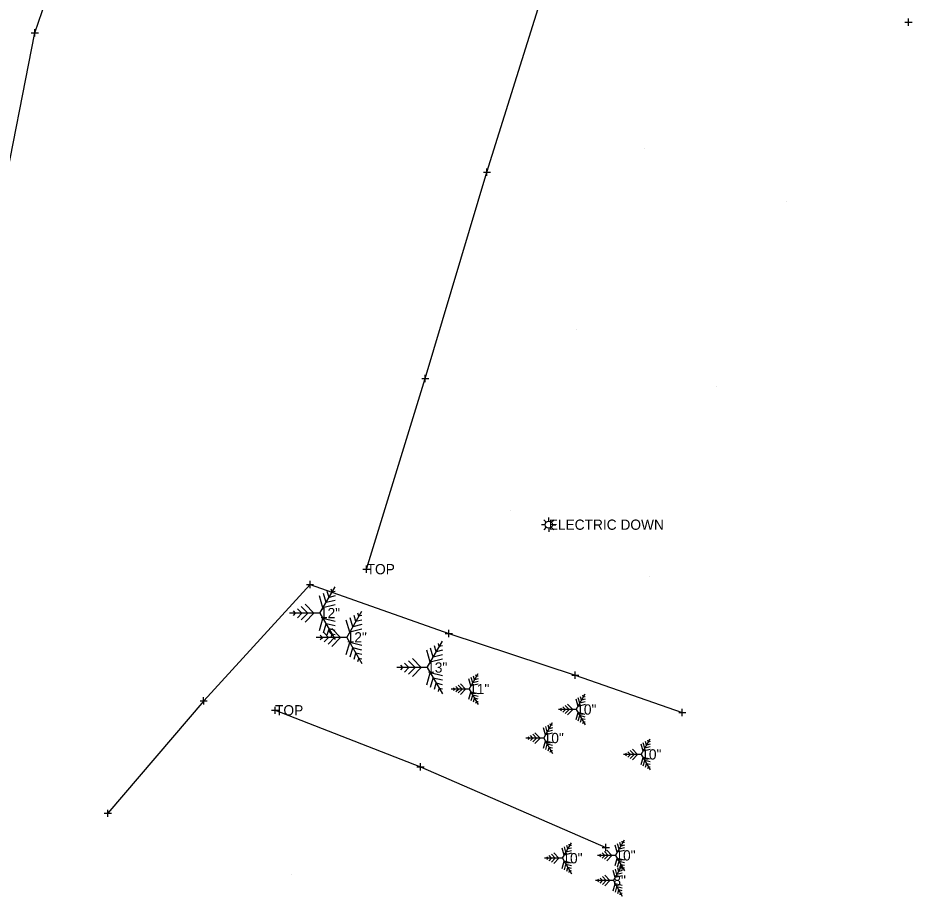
# Model space of a CAD drawing. Extents: x 1733239 to 1734352, y 466612 to 468622.
# Drawn here: x 1733888.4 to 1734045.2, y 467838.1 to 467992.2 of the extents above; entities that cross this region are included whole.
import ezdxf

# ---------------------------------------------------------------- set-up
doc = ezdxf.new("R2010")
doc.units = 0
for name, color, linetype in [('S_Terrain_Boundary', 7, 'Continuous'), ('S_Terrain_High_Points', 7, 'Continuous'), ('S_Terrain_Holes', 7, 'Continuous'), ('S_Terrain_Islands', 7, 'Continuous'), ('S_Terrain_Low_Points', 7, 'Continuous'), ('S_Terrain_Major_Contours', 7, 'Continuous'), ('S_Terrain_Major_Contours_Label', 7, 'Continuous'), ('S_Terrain_Minor_Contours', 7, 'Continuous'), ('S_Traffic_Sign_SinglePost', 7, 'Continuous')]:
    doc.layers.add(name, color=color, linetype=linetype)

msp = doc.modelspace()

# ---------------------------------------------------------------- linework, layer by layer
at = {"layer": 'S_Terrain_Boundary'}
for points in [[(1733939.58, 467892.77), (1733920.94, 467872.37), (1733904.15, 467852.65)], [(1733939.58, 467892.77), (1733963.92, 467884.2), (1733986.1, 467876.86), (1734004.85, 467870.32)]]:
    msp.add_lwpolyline(points, dxfattribs=at)
at = {"layer": 'S_Terrain_High_Points'}
for p, q in [((1733941.32, 467887.77), (1733943.98, 467892.38)), ((1733941.85, 467888.69), (1733941.24, 467890.79)), ((1733942.39, 467889.61), (1733941.93, 467891.19)), ((1733942.91, 467890.53), (1733942.61, 467891.59)), ((1733943.98, 467890.79), (1733942.91, 467890.53)), ((1733943.45, 467891.45), (1733943.3, 467891.98)), ((1733943.98, 467891.59), (1733943.45, 467891.45)), ((1733939.19, 467887.77), (1733938.05, 467888.95)), ((1733940.25, 467887.77), (1733938.73, 467889.35)), ((1733943.98, 467889.21), (1733941.85, 467888.69)), ((1733943.98, 467890.01), (1733942.39, 467889.61)), ((1733941.32, 467887.77), (1733936, 467887.77)), ((1733937.06, 467887.77), (1733936.68, 467888.16)), ((1733936.68, 467887.37), (1733937.06, 467887.77)), ((1733938.12, 467887.77), (1733937.37, 467888.55)), ((1733937.37, 467886.97), (1733938.12, 467887.77)), ((1733938.05, 467886.58), (1733939.19, 467887.77)), ((1733938.73, 467886.18), (1733940.25, 467887.77)), ((1733941.32, 467887.77), (1733943.98, 467883.15)), ((1733946.01, 467883.52), (1733948.67, 467888.13)), ((1733948.13, 467887.21), (1733947.98, 467887.74)), ((1733941.24, 467884.74), (1733941.85, 467886.84)), ((1733943.98, 467886.32), (1733941.85, 467886.84)), ((1733941.93, 467884.34), (1733942.39, 467885.92)), ((1733943.98, 467885.52), (1733942.39, 467885.92)), ((1733946.54, 467884.44), (1733945.93, 467886.55)), ((1733947.07, 467885.36), (1733946.61, 467886.94)), ((1733947.6, 467886.28), (1733947.3, 467887.34)), ((1733948.67, 467886.55), (1733947.6, 467886.28)), ((1733948.67, 467887.34), (1733948.13, 467887.21)), ((1733942.81, 467883.52), (1733942.05, 467884.31)), ((1733942.61, 467883.94), (1733942.91, 467885)), ((1733943.88, 467883.52), (1733942.74, 467884.7)), ((1733943.98, 467884.74), (1733942.91, 467885)), ((1733944.94, 467883.52), (1733943.42, 467885.1)), ((1733948.67, 467884.97), (1733946.54, 467884.44)), ((1733948.67, 467885.76), (1733947.07, 467885.36)), ((1733946.01, 467883.52), (1733940.68, 467883.52)), ((1733941.74, 467883.52), (1733941.37, 467883.91)), ((1733941.37, 467883.12), (1733941.74, 467883.52)), ((1733942.05, 467882.73), (1733942.81, 467883.52)), ((1733942.74, 467882.33), (1733943.88, 467883.52)), ((1733943.3, 467883.55), (1733943.45, 467884.08)), ((1733943.42, 467881.94), (1733944.94, 467883.52)), ((1733943.98, 467883.94), (1733943.45, 467884.08)), ((1733946.01, 467883.52), (1733948.67, 467878.91)), ((1733960.12, 467878.23), (1733962.79, 467882.84)), ((1733945.93, 467880.49), (1733946.54, 467882.6)), ((1733948.67, 467882.07), (1733946.54, 467882.6)), ((1733946.61, 467880.09), (1733947.07, 467881.67)), ((1733948.67, 467881.28), (1733947.07, 467881.67)), ((1733960.66, 467879.15), (1733960.05, 467881.25)), ((1733961.19, 467880.07), (1733960.73, 467881.65)), ((1733961.72, 467880.99), (1733961.42, 467882.05)), ((1733962.79, 467881.25), (1733961.72, 467880.99)), ((1733962.25, 467881.91), (1733962.1, 467882.44)), ((1733962.79, 467882.05), (1733962.25, 467881.91)), ((1733947.3, 467879.7), (1733947.6, 467880.75)), ((1733948.67, 467880.49), (1733947.6, 467880.75)), ((1733947.98, 467879.3), (1733948.13, 467879.83)), ((1733948.67, 467879.7), (1733948.13, 467879.83)), ((1733959.06, 467878.23), (1733957.54, 467879.81)), ((1733962.79, 467879.67), (1733960.66, 467879.15)), ((1733962.79, 467880.47), (1733961.19, 467880.07)), ((1733960.12, 467878.23), (1733954.8, 467878.23)), ((1733955.86, 467878.23), (1733955.49, 467878.62)), ((1733955.49, 467877.83), (1733955.86, 467878.23)), ((1733956.93, 467878.23), (1733956.17, 467879.01)), ((1733956.17, 467877.43), (1733956.93, 467878.23)), ((1733958, 467878.23), (1733956.85, 467879.41)), ((1733956.85, 467877.04), (1733958, 467878.23)), ((1733957.54, 467876.64), (1733959.06, 467878.23)), ((1733960.12, 467878.23), (1733962.79, 467873.62)), ((1733960.05, 467875.2), (1733960.66, 467877.3)), ((1733962.79, 467876.78), (1733960.66, 467877.3)), ((1733960.73, 467874.8), (1733961.19, 467876.38)), ((1733962.79, 467875.99), (1733961.19, 467876.38)), ((1733961.42, 467874.4), (1733961.72, 467875.46)), ((1733962.79, 467875.2), (1733961.72, 467875.46)), ((1733962.1, 467874.01), (1733962.25, 467874.54)), ((1733962.79, 467874.4), (1733962.25, 467874.54))]:
    msp.add_line(p, q, dxfattribs=at)
at = {"layer": 'S_Terrain_Holes'}
for points in [[(1733853.36, 467859.67), (1733863.53, 467892.27), (1733873.85, 467924.74), (1733885.4, 467959.39), (1733891.32, 467989.61), (1733902.91, 468023.32), (1733917.22, 468057.86), (1733927.15, 468090.49), (1733931.35, 468108.36)], [(1733949.51, 467895.49), (1733959.79, 467928.95), (1733970.61, 467965.17), (1733979.86, 467994.8), (1733982.14, 468008.65)], [(1733933.45, 467870.72), (1733958.96, 467860.82), (1733991.46, 467846.63)]]:
    msp.add_lwpolyline(points, dxfattribs=at)
at = {"layer": 'S_Terrain_Islands'}
msp.add_line((1734044.52, 467991.47), (1734044.52, 467991.47), dxfattribs=at)
at = {"layer": 'S_Terrain_Low_Points'}
for p, q in [((1733967.49, 467874.45), (1733969.06, 467877.17)), ((1733968.12, 467875.54), (1733967.85, 467876.47)), ((1733968.43, 467876.08), (1733968.25, 467876.71)), ((1733968.75, 467876.63), (1733968.66, 467876.94)), ((1733969.06, 467876.71), (1733968.75, 467876.63)), ((1733965.61, 467874.45), (1733965.16, 467874.92)), ((1733966.23, 467874.45), (1733965.56, 467875.15)), ((1733966.86, 467874.45), (1733965.97, 467875.39)), ((1733967.8, 467875), (1733967.45, 467876.24)), ((1733969.06, 467875.31), (1733967.8, 467875)), ((1733969.06, 467875.77), (1733968.12, 467875.54)), ((1733969.06, 467876.24), (1733968.43, 467876.08)), ((1733967.49, 467874.45), (1733964.35, 467874.45)), ((1733964.98, 467874.45), (1733964.76, 467874.69)), ((1733964.76, 467874.22), (1733964.98, 467874.45)), ((1733965.16, 467873.99), (1733965.61, 467874.45)), ((1733965.56, 467873.76), (1733966.23, 467874.45)), ((1733965.97, 467873.52), (1733966.86, 467874.45)), ((1733967.45, 467872.67), (1733967.8, 467873.91)), ((1733967.49, 467874.45), (1733969.06, 467871.74)), ((1733969.06, 467873.6), (1733967.8, 467873.91)), ((1733967.85, 467872.44), (1733968.12, 467873.37)), ((1733969.06, 467873.14), (1733968.12, 467873.37)), ((1733986.26, 467870.86), (1733987.83, 467873.58)), ((1733987.52, 467873.03), (1733987.43, 467873.35)), ((1733968.25, 467872.2), (1733968.43, 467872.82)), ((1733969.06, 467872.67), (1733968.43, 467872.82)), ((1733968.66, 467871.97), (1733968.75, 467872.28)), ((1733969.06, 467872.2), (1733968.75, 467872.28)), ((1733985.64, 467870.86), (1733984.74, 467871.8)), ((1733986.58, 467871.4), (1733986.22, 467872.65)), ((1733987.83, 467871.72), (1733986.58, 467871.4)), ((1733986.89, 467871.95), (1733986.62, 467872.88)), ((1733987.83, 467872.18), (1733986.89, 467871.95)), ((1733987.21, 467872.49), (1733987.03, 467873.11)), ((1733987.83, 467872.65), (1733987.21, 467872.49)), ((1733987.83, 467873.11), (1733987.52, 467873.03)), ((1733986.26, 467870.86), (1733983.13, 467870.86)), ((1733983.76, 467870.86), (1733983.53, 467871.09)), ((1733983.53, 467870.63), (1733983.76, 467870.86)), ((1733984.38, 467870.86), (1733983.93, 467871.33)), ((1733983.93, 467870.4), (1733984.38, 467870.86)), ((1733985.01, 467870.86), (1733984.34, 467871.56)), ((1733984.34, 467870.17), (1733985.01, 467870.86)), ((1733984.74, 467869.93), (1733985.64, 467870.86)), ((1733986.22, 467869.08), (1733986.58, 467870.32)), ((1733986.26, 467870.86), (1733987.83, 467868.15)), ((1733987.83, 467870.01), (1733986.58, 467870.32)), ((1733980.55, 467865.85), (1733982.12, 467868.57)), ((1733986.62, 467868.85), (1733986.89, 467869.78)), ((1733987.83, 467869.54), (1733986.89, 467869.78)), ((1733987.03, 467868.61), (1733987.21, 467869.23)), ((1733987.83, 467869.08), (1733987.21, 467869.23)), ((1733987.43, 467868.38), (1733987.52, 467868.69)), ((1733987.83, 467868.61), (1733987.52, 467868.69)), ((1733980.86, 467866.4), (1733980.5, 467867.64)), ((1733981.17, 467866.94), (1733980.91, 467867.87)), ((1733982.12, 467867.17), (1733981.17, 467866.94)), ((1733981.49, 467867.48), (1733981.31, 467868.11)), ((1733982.12, 467867.64), (1733981.49, 467867.48)), ((1733981.8, 467868.03), (1733981.71, 467868.34)), ((1733982.12, 467868.11), (1733981.8, 467868.03)), ((1733980.55, 467865.85), (1733977.41, 467865.85)), ((1733978.04, 467865.85), (1733977.81, 467866.09)), ((1733977.81, 467865.62), (1733978.04, 467865.85)), ((1733978.67, 467865.85), (1733978.22, 467866.32)), ((1733978.22, 467865.39), (1733978.67, 467865.85)), ((1733979.29, 467865.85), (1733978.62, 467866.55)), ((1733978.62, 467865.16), (1733979.29, 467865.85)), ((1733979.92, 467865.85), (1733979.02, 467866.79)), ((1733979.02, 467864.92), (1733979.92, 467865.85)), ((1733980.55, 467865.85), (1733982.12, 467863.14)), ((1733982.12, 467866.71), (1733980.86, 467866.4)), ((1733997.66, 467862.98), (1733999.23, 467865.7)), ((1733998.92, 467865.15), (1733998.83, 467865.46)), ((1733980.5, 467864.07), (1733980.86, 467865.31)), ((1733982.12, 467865), (1733980.86, 467865.31)), ((1733980.91, 467863.84), (1733981.17, 467864.77)), ((1733982.12, 467864.53), (1733981.17, 467864.77)), ((1733981.31, 467863.6), (1733981.49, 467864.22)), ((1733982.12, 467864.07), (1733981.49, 467864.22)), ((1733997.03, 467862.98), (1733996.14, 467863.91)), ((1733997.98, 467863.52), (1733997.62, 467864.77)), ((1733998.29, 467864.07), (1733998.02, 467865)), ((1733999.23, 467864.3), (1733998.29, 467864.07)), ((1733998.6, 467864.61), (1733998.43, 467865.23)), ((1733999.23, 467864.77), (1733998.6, 467864.61)), ((1733999.23, 467865.23), (1733998.92, 467865.15)), ((1733981.71, 467863.37), (1733981.8, 467863.68)), ((1733982.12, 467863.6), (1733981.8, 467863.68)), ((1733997.66, 467862.98), (1733994.53, 467862.98)), ((1733995.15, 467862.98), (1733994.93, 467863.21)), ((1733994.93, 467862.75), (1733995.15, 467862.98)), ((1733995.78, 467862.98), (1733995.33, 467863.45)), ((1733995.33, 467862.52), (1733995.78, 467862.98)), ((1733996.41, 467862.98), (1733995.74, 467863.68)), ((1733995.74, 467862.28), (1733996.41, 467862.98)), ((1733996.14, 467862.05), (1733997.03, 467862.98)), ((1733997.62, 467861.2), (1733997.98, 467862.44)), ((1733997.66, 467862.98), (1733999.23, 467860.26)), ((1733999.23, 467863.84), (1733997.98, 467863.52)), ((1733999.23, 467862.13), (1733997.98, 467862.44)), ((1733998.02, 467860.96), (1733998.29, 467861.89)), ((1733999.23, 467861.66), (1733998.29, 467861.89)), ((1733998.43, 467860.73), (1733998.6, 467861.35)), ((1733999.23, 467861.2), (1733998.6, 467861.35)), ((1733998.83, 467860.5), (1733998.92, 467860.81)), ((1733999.23, 467860.73), (1733998.92, 467860.81)), ((1733983.83, 467844.76), (1733985.4, 467847.48)), ((1733984.46, 467845.85), (1733984.19, 467846.78)), ((1733984.77, 467846.39), (1733984.59, 467847.01)), ((1733985.09, 467846.93), (1733985, 467847.25)), ((1733985.4, 467847.01), (1733985.09, 467846.93)), ((1733993.45, 467845.81), (1733993.09, 467847.05)), ((1733993.13, 467845.26), (1733994.7, 467847.98)), ((1733993.76, 467846.35), (1733993.49, 467847.28)), ((1733994.08, 467846.89), (1733993.9, 467847.52)), ((1733994.7, 467847.05), (1733994.08, 467846.89)), ((1733994.39, 467847.44), (1733994.3, 467847.75)), ((1733994.7, 467847.52), (1733994.39, 467847.44)), ((1733981.95, 467844.76), (1733981.5, 467845.23)), ((1733982.58, 467844.76), (1733981.9, 467845.46)), ((1733983.2, 467844.76), (1733982.31, 467845.69)), ((1733984.14, 467845.3), (1733983.79, 467846.55)), ((1733985.4, 467845.62), (1733984.14, 467845.3)), ((1733985.4, 467846.08), (1733984.46, 467845.85)), ((1733985.4, 467846.55), (1733984.77, 467846.39)), ((1733993.13, 467845.26), (1733990, 467845.26)), ((1733990.63, 467845.26), (1733990.4, 467845.5)), ((1733990.4, 467845.03), (1733990.63, 467845.26)), ((1733991.25, 467845.26), (1733990.8, 467845.73)), ((1733990.8, 467844.8), (1733991.25, 467845.26)), ((1733991.88, 467845.26), (1733991.21, 467845.96)), ((1733991.21, 467844.57), (1733991.88, 467845.26)), ((1733992.51, 467845.26), (1733991.61, 467846.2)), ((1733991.61, 467844.33), (1733992.51, 467845.26)), ((1733993.13, 467845.26), (1733994.7, 467842.55)), ((1733994.7, 467846.12), (1733993.45, 467845.81)), ((1733994.7, 467846.58), (1733993.76, 467846.35)), ((1733983.83, 467844.76), (1733980.69, 467844.76)), ((1733981.32, 467844.76), (1733981.1, 467844.99)), ((1733981.1, 467844.53), (1733981.32, 467844.76)), ((1733981.5, 467844.3), (1733981.95, 467844.76)), ((1733981.9, 467844.06), (1733982.58, 467844.76)), ((1733982.31, 467843.83), (1733983.2, 467844.76)), ((1733983.79, 467842.98), (1733984.14, 467844.22)), ((1733983.83, 467844.76), (1733985.4, 467842.05)), ((1733985.4, 467843.91), (1733984.14, 467844.22)), ((1733984.19, 467842.75), (1733984.46, 467843.67)), ((1733985.4, 467843.44), (1733984.46, 467843.67)), ((1733992.77, 467840.83), (1733994.34, 467843.54)), ((1733993.09, 467843.48), (1733993.45, 467844.72)), ((1733994.7, 467844.41), (1733993.45, 467844.72)), ((1733993.49, 467843.25), (1733993.76, 467844.18)), ((1733994.7, 467843.95), (1733993.76, 467844.18)), ((1733993.9, 467843.01), (1733994.08, 467843.63)), ((1733994.7, 467843.48), (1733994.08, 467843.63)), ((1733984.59, 467842.51), (1733984.77, 467843.13)), ((1733985.4, 467842.98), (1733984.77, 467843.13)), ((1733985, 467842.28), (1733985.09, 467842.59)), ((1733985.4, 467842.51), (1733985.09, 467842.59)), ((1733993.09, 467841.37), (1733992.73, 467842.61)), ((1733993.4, 467841.91), (1733993.13, 467842.85)), ((1733994.34, 467842.15), (1733993.4, 467841.91)), ((1733993.71, 467842.46), (1733993.54, 467843.08)), ((1733994.34, 467842.61), (1733993.71, 467842.46)), ((1733994.03, 467843), (1733993.94, 467843.31)), ((1733994.34, 467843.08), (1733994.03, 467843)), ((1733994.3, 467842.78), (1733994.39, 467843.09)), ((1733994.7, 467843.01), (1733994.39, 467843.09)), ((1733992.77, 467840.83), (1733989.64, 467840.83)), ((1733990.26, 467840.83), (1733990.04, 467841.06)), ((1733990.04, 467840.59), (1733990.26, 467840.83)), ((1733990.89, 467840.83), (1733990.44, 467841.29)), ((1733990.44, 467840.36), (1733990.89, 467840.83)), ((1733991.52, 467840.83), (1733990.85, 467841.53)), ((1733990.85, 467840.13), (1733991.52, 467840.83)), ((1733992.14, 467840.83), (1733991.25, 467841.76)), ((1733991.25, 467839.9), (1733992.14, 467840.83)), ((1733992.77, 467840.83), (1733994.34, 467838.11)), ((1733994.34, 467841.68), (1733993.09, 467841.37)), ((1733992.73, 467839.04), (1733993.09, 467840.28)), ((1733994.34, 467839.97), (1733993.09, 467840.28)), ((1733993.13, 467838.81), (1733993.4, 467839.74)), ((1733994.34, 467839.51), (1733993.4, 467839.74)), ((1733993.54, 467838.58), (1733993.71, 467839.2)), ((1733994.34, 467839.04), (1733993.71, 467839.2)), ((1733993.94, 467838.34), (1733994.03, 467838.65)), ((1733994.34, 467838.58), (1733994.03, 467838.65))]:
    msp.add_line(p, q, dxfattribs=at)
at = {"layer": 'S_Terrain_Major_Contours'}
for p, q in [((1733998.25, 467969.29), (1733998.25, 467969.29)), ((1734023.08, 467960.04), (1734023.08, 467960.04)), ((1733986.34, 467937.53), (1733986.34, 467937.53)), ((1734010.78, 467927.6), (1734010.78, 467927.6)), ((1733974.68, 467905.72), (1733974.68, 467905.72)), ((1733999.16, 467894.26), (1733999.16, 467894.26)), ((1733936.26, 467841.88), (1733936.26, 467841.88))]:
    msp.add_line(p, q, dxfattribs=at)
at = {"layer": 'S_Terrain_Major_Contours_Label'}
for p, q in [((1733980.82, 467903.29), (1733980.19, 467903.29)), ((1733981, 467903.73), (1733980.56, 467904.17)), ((1733981.44, 467903.92), (1733981.44, 467904.54)), ((1733981.88, 467903.73), (1733982.32, 467904.17)), ((1733982.06, 467903.29), (1733982.69, 467903.29)), ((1733981, 467902.85), (1733980.56, 467902.41)), ((1733981.44, 467902.67), (1733981.44, 467902.04)), ((1733981.88, 467902.85), (1733982.32, 467902.41))]:
    msp.add_line(p, q, dxfattribs=at)
msp.add_circle((1733981.44, 467903.29), 0.624, dxfattribs=at)
at = {"layer": 'S_Terrain_Minor_Contours'}
for p, q in [((1734043.88, 467991.47), (1734045.15, 467991.48)), ((1734044.52, 467990.84), (1734044.51, 467992.11)), ((1734044.52, 467991.47), (1734044.52, 467991.47)), ((1733890.68, 467989.61), (1733891.95, 467989.61)), ((1733891.32, 467988.98), (1733891.31, 467990.25)), ((1733891.32, 467989.61), (1733891.32, 467989.61)), ((1733970.61, 467964.53), (1733970.61, 467965.81)), ((1733969.97, 467965.17), (1733971.25, 467965.17)), ((1733970.61, 467965.17), (1733970.61, 467965.17)), ((1733959.16, 467928.95), (1733960.43, 467928.95)), ((1733959.79, 467928.31), (1733959.79, 467929.58)), ((1733959.79, 467928.95), (1733959.79, 467928.95)), ((1733948.87, 467895.49), (1733950.15, 467895.49)), ((1733949.51, 467894.85), (1733949.51, 467896.12)), ((1733949.51, 467895.49), (1733949.51, 467895.49)), ((1733938.94, 467892.77), (1733940.21, 467892.77)), ((1733938.94, 467892.77), (1733940.21, 467892.77)), ((1733939.58, 467892.14), (1733939.58, 467893.41)), ((1733939.58, 467892.14), (1733939.58, 467893.41)), ((1733939.58, 467892.77), (1733939.58, 467892.77)), ((1733939.58, 467892.77), (1733939.58, 467892.77)), ((1733963.92, 467883.57), (1733963.91, 467884.84)), ((1733963.28, 467884.2), (1733964.55, 467884.21)), ((1733963.92, 467884.2), (1733963.92, 467884.2)), ((1733985.46, 467876.86), (1733986.73, 467876.86)), ((1733986.1, 467876.23), (1733986.1, 467877.5)), ((1733986.1, 467876.86), (1733986.1, 467876.86)), ((1733920.3, 467872.37), (1733921.57, 467872.38)), ((1733920.94, 467871.74), (1733920.93, 467873.01)), ((1733920.94, 467872.37), (1733920.94, 467872.37)), ((1733932.82, 467870.72), (1733934.09, 467870.72)), ((1733933.45, 467870.08), (1733933.45, 467871.35)), ((1733933.45, 467870.72), (1733933.45, 467870.72)), ((1734004.22, 467870.32), (1734005.49, 467870.32)), ((1734004.85, 467869.68), (1734004.85, 467870.95)), ((1734004.85, 467870.32), (1734004.85, 467870.32)), ((1733958.33, 467860.82), (1733959.6, 467860.82)), ((1733958.96, 467860.18), (1733958.96, 467861.45)), ((1733958.96, 467860.82), (1733958.96, 467860.82)), ((1733904.15, 467852.01), (1733904.15, 467853.28)), ((1733903.51, 467852.65), (1733904.79, 467852.65)), ((1733904.15, 467852.65), (1733904.15, 467852.65)), ((1733990.82, 467846.63), (1733992.1, 467846.64)), ((1733991.46, 467846), (1733991.46, 467847.27)), ((1733991.46, 467846.63), (1733991.46, 467846.63))]:
    msp.add_line(p, q, dxfattribs=at)

# ---------------------------------------------------------------- texts
at = {"layer": 'S_Traffic_Sign_SinglePost'}
for s, p in [('ELECTRIC DOWN', (1733981.44, 467902.39)), ('TOP', (1733949.51, 467894.59)), ('12"', (1733941.32, 467886.87)), ('12"', (1733946.01, 467882.62)), ('13"', (1733960.12, 467877.33)), ('11"', (1733967.49, 467873.55)), ('10"', (1733986.26, 467869.96)), ('TOP', (1733933.45, 467869.82)), ('10"', (1733980.55, 467864.95)), ('10"', (1733997.66, 467862.08)), ('10"', (1733983.83, 467843.86)), ('10"', (1733993.13, 467844.36)), ('8"', (1733992.77, 467839.93))]:
    msp.add_text(s, height=1.8, dxfattribs=at).set_placement(p)

doc.saveas('drawing.dxf')
